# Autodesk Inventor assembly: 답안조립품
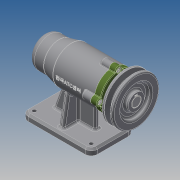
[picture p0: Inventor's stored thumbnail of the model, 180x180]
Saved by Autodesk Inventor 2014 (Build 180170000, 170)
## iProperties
Created: 2019-07
Part Number: 답안조립품
Document SubType Name: Assembly
Designer: kb542-14
Author: kb542-14
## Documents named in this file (12)
- C:\Users\kb542-14\Desktop\490704V1070\답안조립품.iam
- C:\Users\kb542-14\Desktop\490704V1070\본체.ipt
- C:\Users\kb542-14\Desktop\490704V1070\축.ipt
- C:\Users\kb542-14\Desktop\490704V1070\키 5 x 5 x 16.ipt
- C:\Users\kb542-14\Desktop\490704V1070\베어링 6004.ipt
- C:\Users\kb542-14\Desktop\490704V1070\커버.ipt
- C:\Users\kb542-14\Desktop\490704V1070\어댑터슬리브.ipt
- C:\Users\kb542-14\Desktop\490704V1070\볼트 M4.ipt
- C:\Users\kb542-14\Desktop\490704V1070\베어링 51202.ipt
- C:\Users\kb542-14\Desktop\490704V1070\오일 실.ipt
- C:\Users\kb542-14\Desktop\490704V1070\멈춤나사 M3.ipt
- C:\Users\kb542-14\Desktop\490704V1070\V벨트풀리.ipt
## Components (1 placed, 1 different names)
1. V벨트풀리:1
